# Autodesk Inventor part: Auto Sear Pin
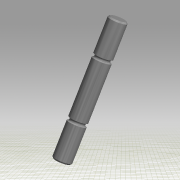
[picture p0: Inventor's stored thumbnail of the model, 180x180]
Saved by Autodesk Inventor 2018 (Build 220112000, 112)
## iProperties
Part Number: Auto Sear Pin
Material: Steel
Document SubType Name: Modeling
Designer: johne
Density: 7.85 g/cm^3
Appearance: Default
Author: johne
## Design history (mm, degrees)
feature "Solid1"
body "Solid2"
